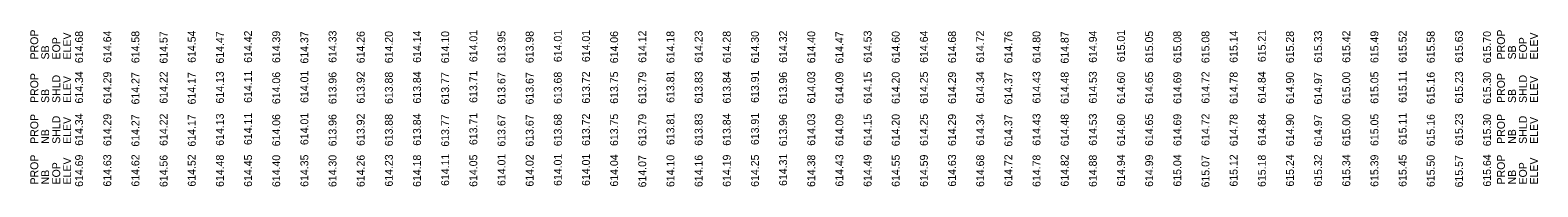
# Model space of a CAD drawing. Extents: x 18039 to 19377, y -378 to 1020.
# Drawn here: x 18039 to 19377, y -378 to -239 of the extents above; entities that cross this region are included whole.
import ezdxf

# ---------------------------------------------------------------- set-up
doc = ezdxf.new("R2010")
doc.units = 0
for name, color, linetype in [('PF_P_Text', 7, 'Continuous'), ('PF_P_Text_Strip_Grades_20', 7, 'Continuous'), ('PF_P_Text_Strip_Grades_LT', 7, 'Continuous'), ('PF_P_Text_Strip_Grades_RT', 7, 'Continuous')]:
    doc.layers.add(name, color=color, linetype=linetype)

msp = doc.modelspace()

# ---------------------------------------------------------------- texts
at = {"layer": 'PF_P_Text'}
for s, p in [('PROP ', (18045.9, -264.9)), ('PROP ', (19348, -264.9)), ('SB ', (18055.6, -264.9)), ('EOP', (18065.4, -264.9)), ('ELEV', (18075.1, -264.9)), ('SB ', (19357.8, -264.9)), ('EOP', (19367.5, -264.9)), ('ELEV', (19377.3, -264.9)), ('PROP ', (18045.9, -303.6)), ('SHLD ', (18065.4, -303.6)), ('ELEV', (18075.1, -303.6)), ('PROP ', (19348, -303.6)), ('SHLD', (19367.5, -303.6)), ('ELEV', (19377.3, -303.6)), ('SB ', (18055.6, -303.6)), ('SB ', (19357.8, -303.6)), ('PROP ', (18045.9, -339.9)), ('SHLD', (18065.4, -339.9)), ('ELEV', (18075.1, -339.9)), ('PROP ', (19348, -339.9)), ('SHLD', (19367.5, -339.9)), ('ELEV', (19377.3, -339.9)), ('NB ', (18055.6, -339.9)), ('NB ', (19357.8, -339.9)), ('PROP ', (18045.9, -376)), ('EOP', (18065.4, -376)), ('ELEV', (18075.1, -376)), ('PROP ', (19348, -376)), ('EOP', (19367.5, -376)), ('ELEV', (19377.3, -376)), ('NB ', (18055.6, -376)), ('NB ', (19357.8, -376))]:
    msp.add_text(s, height=7, rotation=90, dxfattribs=at).set_placement(p)
at = {"layer": 'PF_P_Text_Strip_Grades_20'}
for s, p in [('614.34', (18085.7, -304.1)), ('614.29', (18110.7, -304.4)), ('614.27', (18135.7, -304.9)), ('614.22', (18160.7, -304.2)), ('614.17', (18185.7, -304.9)), ('614.13', (18210.7, -304.1)), ('614.11', (18235.7, -303.5)), ('614.06', (18260.7, -304.6)), ('614.01', (18285.7, -303.5)), ('613.96', (18310.7, -304.6)), ('613.92', (18335.7, -304.2)), ('613.88', (18360.7, -304.5)), ('613.84', (18385.7, -304.1)), ('613.77', (18410.7, -304.9)), ('613.71', (18435.7, -303.5)), ('613.67', (18460.7, -304.9)), ('613.67', (18485.7, -304.9)), ('613.68', (18510.7, -304.5)), ('613.72', (18535.7, -304.2)), ('613.75', (18560.7, -304.3)), ('613.79', (18585.7, -304.4)), ('613.81', (18610.7, -303.5)), ('613.83', (18635.7, -304.1)), ('613.84', (18660.7, -304.1)), ('613.91', (18685.7, -303.5)), ('613.96', (18710.7, -304.6)), ('614.03', (18735.7, -304.1)), ('614.09', (18760.7, -304.4)), ('614.15', (18785.7, -304.3)), ('614.20', (18810.7, -304.5)), ('614.25', (18835.7, -304.3)), ('614.29', (18860.7, -304.4)), ('614.34', (18885.7, -304.1)), ('614.37', (18910.7, -304.9)), ('614.43', (18935.7, -304.1)), ('614.48', (18960.7, -304.5)), ('614.53', (18985.7, -304.1)), ('614.60', (19010.7, -304.5)), ('614.65', (19035.7, -304.3)), ('614.69', (19060.7, -304.4)), ('614.72', (19085.7, -304.2)), ('614.78', (19110.7, -304.5)), ('614.84', (19135.7, -304.1)), ('614.90', (19160.7, -304.5)), ('614.97', (19185.7, -304.9)), ('615.00', (19210.7, -304.5)), ('615.05', (19235.7, -304.3)), ('615.11', (19260.7, -303.5)), ('615.16', (19285.7, -304.6)), ('615.23', (19310.7, -304.1)), ('615.30', (19335.7, -304.5)), ('614.34', (18085.7, -341.6)), ('614.29', (18110.7, -341.9)), ('614.27', (18135.7, -342.4)), ('614.22', (18160.7, -341.7)), ('614.17', (18185.7, -342.4)), ('614.13', (18210.7, -341.6)), ('614.11', (18235.7, -341)), ('614.06', (18260.7, -342.1)), ('614.01', (18285.7, -341)), ('613.96', (18310.7, -342.1)), ('613.92', (18335.7, -341.7)), ('613.88', (18360.7, -342)), ('613.84', (18385.7, -341.6)), ('613.77', (18410.7, -342.4)), ('613.71', (18435.7, -341)), ('613.67', (18460.7, -342.4)), ('613.67', (18485.7, -342.4)), ('613.68', (18510.7, -342)), ('613.72', (18535.7, -341.7)), ('613.75', (18560.7, -341.8)), ('613.79', (18585.7, -341.9)), ('613.81', (18610.7, -341)), ('613.83', (18635.7, -341.6)), ('613.84', (18660.7, -341.6)), ('613.91', (18685.7, -341)), ('613.96', (18710.7, -342.1)), ('614.03', (18735.7, -341.6)), ('614.09', (18760.7, -341.9)), ('614.15', (18785.7, -341.8)), ('614.20', (18810.7, -342)), ('614.25', (18835.7, -341.8)), ('614.29', (18860.7, -341.9)), ('614.34', (18885.7, -341.6)), ('614.37', (18910.7, -342.4)), ('614.43', (18935.7, -341.6)), ('614.48', (18960.7, -342)), ('614.53', (18985.7, -341.6)), ('614.60', (19010.7, -342)), ('614.65', (19035.7, -341.8)), ('614.69', (19060.7, -341.9)), ('614.72', (19085.7, -341.7)), ('614.78', (19110.7, -342)), ('614.84', (19135.7, -341.6)), ('614.90', (19160.7, -342)), ('614.97', (19185.7, -342.4)), ('615.00', (19210.7, -342)), ('615.05', (19235.7, -341.8)), ('615.11', (19260.7, -341)), ('615.16', (19285.7, -342.1)), ('615.23', (19310.7, -341.6)), ('615.30', (19335.7, -342))]:
    msp.add_text(s, height=7, rotation=90, dxfattribs=at).set_placement(p)
at = {"layer": 'PF_P_Text_Strip_Grades_LT'}
for s, p in [('614.68', (18085.7, -268.2)), ('614.64', (18110.7, -267.9)), ('614.58', (18135.7, -268.2)), ('614.57', (18160.7, -268.6)), ('614.54', (18185.7, -267.9)), ('614.47', (18210.7, -268.6)), ('614.42', (18235.7, -267.9)), ('614.39', (18260.7, -268.1)), ('614.37', (18285.7, -268.6)), ('614.33', (18310.7, -267.9)), ('614.26', (18335.7, -268.3)), ('614.20', (18360.7, -268.3)), ('614.14', (18385.7, -267.9)), ('614.10', (18410.7, -268.3)), ('614.01', (18435.7, -267.3)), ('613.95', (18460.7, -268.1)), ('613.98', (18485.7, -268.2)), ('614.01', (18510.7, -267.3)), ('614.01', (18535.7, -267.3)), ('614.06', (18560.7, -268.3)), ('614.12', (18585.7, -267.9)), ('614.18', (18610.7, -268.2)), ('614.23', (18635.7, -267.9)), ('614.28', (18660.7, -268.2)), ('614.30', (18685.7, -268.3)), ('614.32', (18710.7, -267.9)), ('614.40', (18735.7, -268.3)), ('614.47', (18760.7, -268.6)), ('614.53', (18785.7, -267.9)), ('614.60', (18810.7, -268.3)), ('614.64', (18835.7, -267.9)), ('614.68', (18860.7, -268.2)), ('614.72', (18885.7, -267.9)), ('614.76', (18910.7, -268.3)), ('614.80', (18935.7, -268.3)), ('614.87', (18960.7, -268.6)), ('614.94', (18985.7, -267.9)), ('615.01', (19010.7, -267.3)), ('615.05', (19035.7, -268.1)), ('615.08', (19060.7, -268.2)), ('615.08', (19085.7, -268.2)), ('615.14', (19110.7, -267.9)), ('615.21', (19135.7, -267.3)), ('615.28', (19160.7, -268.2)), ('615.33', (19185.7, -267.9)), ('615.42', (19210.7, -267.9)), ('615.49', (19235.7, -268.1)), ('615.52', (19260.7, -267.9)), ('615.58', (19285.7, -268.2)), ('615.63', (19310.7, -267.9)), ('615.70', (19335.7, -268.3))]:
    msp.add_text(s, height=7, rotation=90, dxfattribs=at).set_placement(p)
at = {"layer": 'PF_P_Text_Strip_Grades_RT'}
for s, p in [('614.69', (18085.7, -378.1)), ('614.63', (18110.7, -377.9)), ('614.62', (18135.7, -377.9)), ('614.56', (18160.7, -378.3)), ('614.52', (18185.7, -377.9)), ('614.48', (18210.7, -378.2)), ('614.45', (18235.7, -378.1)), ('614.40', (18260.7, -378.3)), ('614.35', (18285.7, -378.1)), ('614.30', (18310.7, -378.3)), ('614.26', (18335.7, -378.3)), ('614.23', (18360.7, -377.9)), ('614.18', (18385.7, -378.2)), ('614.11', (18410.7, -377.3)), ('614.05', (18435.7, -378.1)), ('614.01', (18460.7, -377.3)), ('614.02', (18485.7, -377.9)), ('614.01', (18510.7, -377.3)), ('614.01', (18535.7, -377.3)), ('614.04', (18560.7, -377.9)), ('614.07', (18585.7, -378.6)), ('614.10', (18610.7, -378.3)), ('614.16', (18635.7, -378.3)), ('614.19', (18660.7, -378.1)), ('614.25', (18685.7, -378.1)), ('614.31', (18710.7, -377.3)), ('614.38', (18735.7, -378.2)), ('614.43', (18760.7, -377.9)), ('614.49', (18785.7, -378.1)), ('614.55', (18810.7, -378.1)), ('614.59', (18835.7, -378.1)), ('614.63', (18860.7, -377.9)), ('614.68', (18885.7, -378.2)), ('614.72', (18910.7, -377.9)), ('614.78', (18935.7, -378.2)), ('614.82', (18960.7, -377.9)), ('614.88', (18985.7, -378.2)), ('614.94', (19010.7, -377.9)), ('614.99', (19035.7, -378.1)), ('615.04', (19060.7, -377.9)), ('615.07', (19085.7, -378.6)), ('615.12', (19110.7, -377.9)), ('615.18', (19135.7, -378.2)), ('615.24', (19160.7, -377.9)), ('615.32', (19185.7, -377.9)), ('615.34', (19210.7, -377.9)), ('615.39', (19235.7, -378.1)), ('615.45', (19260.7, -378.1)), ('615.50', (19285.7, -378.3)), ('615.57', (19310.7, -378.6)), ('615.64', (19335.7, -377.9))]:
    msp.add_text(s, height=7, rotation=90, dxfattribs=at).set_placement(p)

doc.saveas('drawing.dxf')
